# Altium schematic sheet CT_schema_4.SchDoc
size 297 x 173 mm
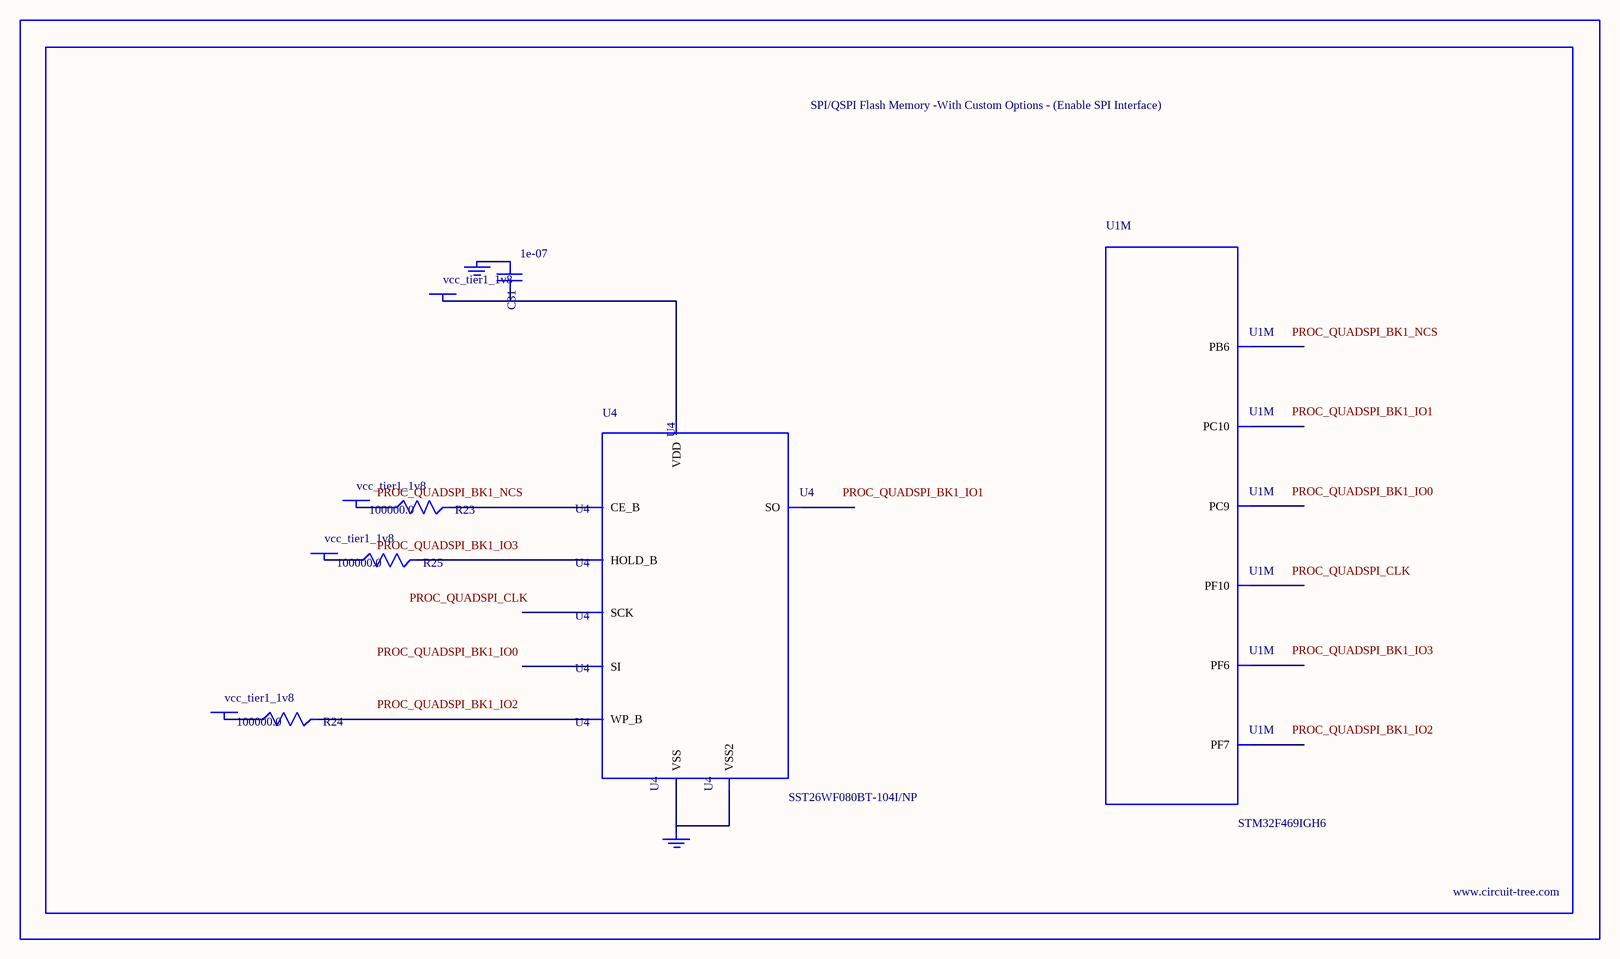
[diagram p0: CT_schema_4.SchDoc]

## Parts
BORDER3  (no value)
C31  1e-07  [C0402]
GND_INSTANCE_3_0  (no value)
GND_INSTANCE_3_1  (no value)
POWER_INSTANCE_3_0  vcc_tier1_1v8
POWER_INSTANCE_3_1  vcc_tier1_1v8
POWER_INSTANCE_3_2  vcc_tier1_1v8
POWER_INSTANCE_3_3  vcc_tier1_1v8
R23  100000.0  [R0603]
R24  100000.0  [R0603]
R25  100000.0  [R0603]
U1  STM32F469IGH6  [UFBGA176]  (part M of 16)
U4  SST26WF080BT-104I/NP  [USON-8]

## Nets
NetC31_1: C31.1 GND_INSTANCE_3_0.0(GND)
NetC31_2: C31.2 POWER_INSTANCE_3_3.0(PWR) U4.8(VDD)
NetGND_INSTANCE_3_1_0: GND_INSTANCE_3_1.0(GND) U4.4(VSS) U4.9(VSS2)
NetPOWER_INSTANCE_3_0_0: POWER_INSTANCE_3_0.0(PWR) R23.1
NetPOWER_INSTANCE_3_1_0: POWER_INSTANCE_3_1.0(PWR) R24.1
NetPOWER_INSTANCE_3_2_0: POWER_INSTANCE_3_2.0(PWR) R25.1
NetR23_2: R23.2 U4.1(CE_B)
NetR24_2: R24.2 U4.3(WP_B)
NetR25_2: R25.2 U4.7(HOLD_B)

Not connected (* = marked no-connect by the designer): U1 B6(PB6) B14(PC10) F14(PC9) K1(PF7) K2(PF6) L1(PF10); U4 2(SO) 5(SI) 6(SCK)

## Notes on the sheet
- Labels drawn without touching a wire or pin: PROC_QUADSPI_BK1_IO0, PROC_QUADSPI_BK1_IO1, PROC_QUADSPI_BK1_IO2, PROC_QUADSPI_BK1_IO3, PROC_QUADSPI_BK1_NCS, PROC_QUADSPI_CLK

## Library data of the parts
BORDER3 = BORDER_PAGE3
C31 = C0402C104K3RACTU
GND_INSTANCE_3_0 GND_INSTANCE_3_1 = GND
POWER_INSTANCE_3_0-POWER_INSTANCE_3_3 = PWR
R23-R25 = RC0603JR-07100KL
